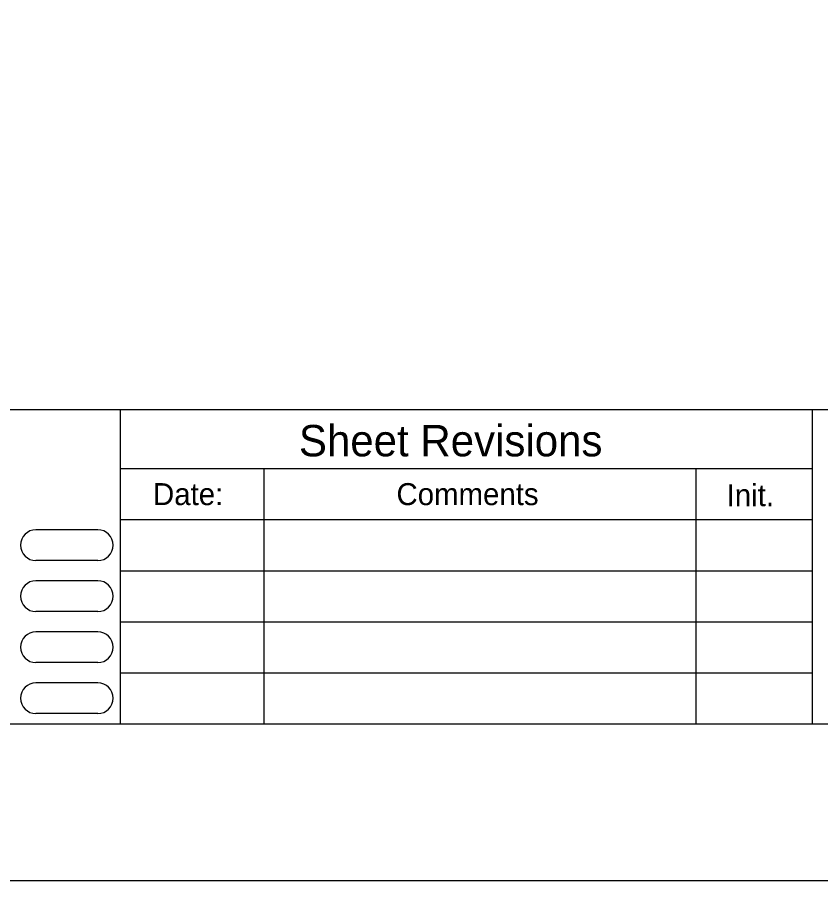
# Model space of a CAD drawing. Extents: x 0 to 1.42, y 0 to 0.92.
# Drawn here: x 0.405 to 0.6182, y 0 to 0.2292 of the extents above; entities that cross this region are included whole.
import ezdxf

# ---------------------------------------------------------------- set-up
doc = ezdxf.new("R2010")
doc.units = 0
for name, color, linetype in [('SHEET_Lines', 7, 'Continuous'), ('SHEET_Plot Boundary', 7, 'Continuous'), ('SHEET_Text-Border Info', 7, 'Continuous'), ('SHEET_Text-Titles', 7, 'Continuous')]:
    doc.layers.add(name, color=color, linetype=linetype)

msp = doc.modelspace()

# ---------------------------------------------------------------- linework, layer by layer
at = {"layer": 'SHEET_Lines'}
for p, q in [((1.375, 0.125), (0.08333, 0.125)), ((0.43238, 0.04167), (0.43238, 0.125)), ((0.61597, 0.04167), (0.61597, 0.125)), ((0.43238, 0.10937), (0.61597, 0.10937)), ((0.47057, 0.04167), (0.47057, 0.10937)), ((0.58516, 0.04167), (0.58516, 0.10937)), ((0.43238, 0.09583), (0.61597, 0.09583)), ((0.42637, 0.09316), (0.40999, 0.09316)), ((0.42637, 0.08497), (0.40999, 0.08497)), ((0.43238, 0.08229), (0.61597, 0.08229)), ((0.42637, 0.07962), (0.40999, 0.07962)), ((0.42637, 0.07143), (0.40999, 0.07143)), ((0.43238, 0.06875), (0.61597, 0.06875)), ((0.42637, 0.06607), (0.40999, 0.06607)), ((0.42637, 0.05788), (0.40999, 0.05788)), ((0.43238, 0.05521), (0.61597, 0.05521)), ((0.42637, 0.05253), (0.40999, 0.05253)), ((0.42637, 0.04434), (0.40999, 0.04434)), ((0.08333, 0.04167), (1.375, 0.04167))]:
    msp.add_line(p, q, dxfattribs=at)
for centre, start, end in [((0.40999, 0.08906), 90, 270), ((0.42637, 0.08906), 270, 90), ((0.40999, 0.07552), 90, 270), ((0.42637, 0.07552), 270, 90), ((0.40999, 0.06198), 90, 270), ((0.42637, 0.06198), 270, 90), ((0.40999, 0.04844), 90, 270), ((0.42637, 0.04844), 270, 90)]:
    msp.add_arc(centre, 0.00409, start, end, dxfattribs=at)
at = {"layer": 'SHEET_Plot Boundary'}
msp.add_lwpolyline([(0, 0.91666), (1.41666, 0.91666), (1.41666, 0), (0, 0)], close=True, dxfattribs=at)

# ---------------------------------------------------------------- texts
at = {"layer": 'SHEET_Text-Border Info'}
for s, p in [('Date:', (0.44104, 0.09969)), ('Comments', (0.50563, 0.09969)), ('Init.', (0.59322, 0.09941))]:
    msp.add_text(s, height=0.005833, dxfattribs=at).set_placement(p)
at = {"layer": 'SHEET_Text-Titles'}
msp.add_text('Sheet Revisions', height=0.0083333, dxfattribs=at).set_placement((0.47975, 0.11263))

doc.saveas('drawing.dxf')
